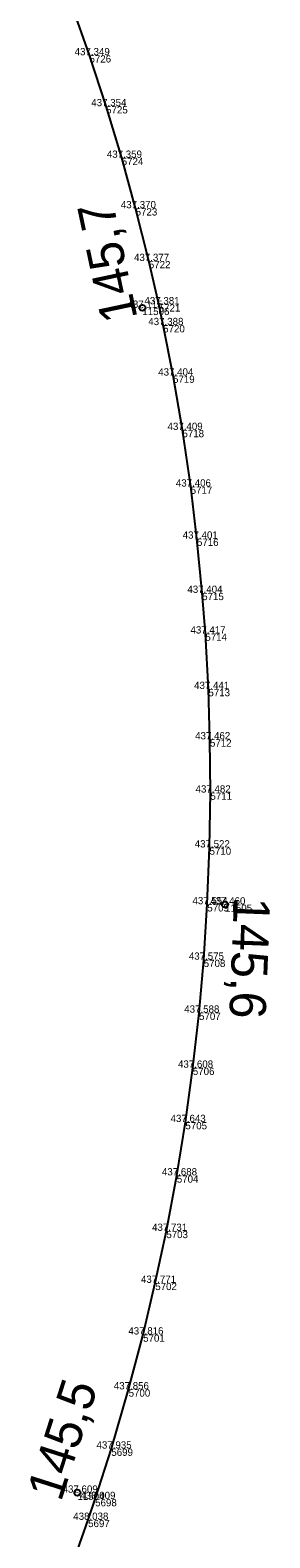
# Model space of a CAD drawing. Extents: x -654154 to -652650, y -1166925 to -1164904.
# Drawn here: x -652689.6 to -652650, y -1166664.4 to -1166415.2 of the extents above; entities that cross this region are included whole.
import ezdxf

# ---------------------------------------------------------------- set-up
doc = ezdxf.new("R2010")
doc.units = 0
for name, color, linetype in [('Vrstva 1', 7, 'Continuous'), ('Vrstva 60', 7, 'Continuous'), ('Vrstva 61', 7, 'Continuous'), ('Vrstva 7', 7, 'Continuous')]:
    doc.layers.add(name, color=color, linetype=linetype)

msp = doc.modelspace()

# ---------------------------------------------------------------- linework, layer by layer
at = {"layer": 'Vrstva 1'}
msp.add_lwpolyline([(-652682.15, -1166667.42), (-652680.05, -1166661.47), (-652678.89, -1166658.03), (-652676.22, -1166649.69), (-652673.36, -1166639.9), (-652670.96, -1166630.83), (-652668.96, -1166622.29), (-652667.13, -1166613.7), (-652665.4, -1166604.53), (-652663.98, -1166595.71), (-652662.75, -1166586.73), (-652661.72, -1166577.63), (-652660.95, -1166568.88), (-652660.36, -1166559.7), (-652659.99, -1166550.32), (-652659.85, -1166541.24), (-652659.92, -1166532.45), (-652660.18, -1166524.12), (-652660.68, -1166514.95), (-652661.2, -1166508.23), (-652662.07, -1166499.27), (-652663.11, -1166490.66), (-652664.47, -1166481.3), (-652666.02, -1166472.31), (-652667.65, -1166463.97), (-652668.38, -1166460.53), (-652670.02, -1166453.37), (-652672.2, -1166444.65), (-652674.5, -1166436.31), (-652677.08, -1166427.78), (-652679.83, -1166419.36), (-652682.76, -1166411.06)], dxfattribs=at)
at = {"layer": 'Vrstva 60'}
for p, q in [((-652679.83, -1166419.36), (-652679.83, -1166419.36)), ((-652677.08, -1166427.78), (-652677.08, -1166427.78)), ((-652674.5, -1166436.31), (-652674.5, -1166436.31)), ((-652672.2, -1166444.65), (-652672.2, -1166444.65)), ((-652670.02, -1166453.37), (-652670.02, -1166453.37)), ((-652671.09, -1166461.11), (-652671.09, -1166461.11)), ((-652668.38, -1166460.53), (-652668.38, -1166460.53)), ((-652667.65, -1166463.97), (-652667.65, -1166463.97)), ((-652666.02, -1166472.31), (-652666.02, -1166472.31)), ((-652664.47, -1166481.3), (-652664.47, -1166481.3)), ((-652663.11, -1166490.66), (-652663.11, -1166490.66)), ((-652662.07, -1166499.27), (-652662.07, -1166499.27)), ((-652661.2, -1166508.23), (-652661.2, -1166508.23)), ((-652660.68, -1166514.95), (-652660.68, -1166514.95)), ((-652660.18, -1166524.12), (-652660.18, -1166524.12)), ((-652659.92, -1166532.45), (-652659.92, -1166532.45)), ((-652659.85, -1166541.24), (-652659.85, -1166541.24)), ((-652659.99, -1166550.32), (-652659.99, -1166550.32)), ((-652660.36, -1166559.7), (-652660.36, -1166559.7)), ((-652657.42, -1166559.75), (-652657.42, -1166559.75)), ((-652660.95, -1166568.88), (-652660.95, -1166568.88)), ((-652661.72, -1166577.63), (-652661.72, -1166577.63)), ((-652662.75, -1166586.73), (-652662.75, -1166586.73)), ((-652663.98, -1166595.71), (-652663.98, -1166595.71)), ((-652665.4, -1166604.53), (-652665.4, -1166604.53)), ((-652667.13, -1166613.7), (-652667.13, -1166613.7)), ((-652668.96, -1166622.29), (-652668.96, -1166622.29)), ((-652670.96, -1166630.83), (-652670.96, -1166630.83)), ((-652673.36, -1166639.9), (-652673.36, -1166639.9)), ((-652676.22, -1166649.69), (-652676.22, -1166649.69)), ((-652681.82, -1166656.98), (-652681.82, -1166656.98)), ((-652678.89, -1166658.03), (-652678.89, -1166658.03)), ((-652680.05, -1166661.47), (-652680.05, -1166661.47))]:
    msp.add_line(p, q, dxfattribs=at)
at = {"layer": 'Vrstva 7'}
for p, q in [((-652671.08, -1166461.15), (-652671.1, -1166461.06)), ((-652657.42, -1166559.7), (-652657.42, -1166559.8)), ((-652681.83, -1166657.02), (-652681.8, -1166656.93))]:
    msp.add_line(p, q, dxfattribs=at)
for centre in [(-652671.09, -1166461.11), (-652657.42, -1166559.75), (-652681.82, -1166656.98)]:
    msp.add_circle(centre, 0.5, dxfattribs=at)

# ---------------------------------------------------------------- texts
at = {"layer": 'Vrstva 60'}
for s, p in [('5726', (-652679.83, -1166420.56)), ('5725', (-652677.08, -1166428.98)), ('5724', (-652674.5, -1166437.51)), ('5723', (-652672.2, -1166445.85)), ('5722', (-652670.02, -1166454.57)), ('11506', (-652671.09, -1166462.31)), ('5721', (-652668.38, -1166461.73)), ('5720', (-652667.65, -1166465.17)), ('5719', (-652666.02, -1166473.51)), ('5718', (-652664.47, -1166482.5)), ('5717', (-652663.11, -1166491.86)), ('5716', (-652662.07, -1166500.47)), ('5715', (-652661.2, -1166509.43)), ('5714', (-652660.68, -1166516.15)), ('5713', (-652660.18, -1166525.32)), ('5712', (-652659.92, -1166533.65)), ('5711', (-652659.85, -1166542.44)), ('5710', (-652659.99, -1166551.52)), ('5709', (-652660.36, -1166560.9)), ('11505', (-652657.42, -1166560.95)), ('5708', (-652660.95, -1166570.08)), ('5707', (-652661.72, -1166578.83)), ('5706', (-652662.75, -1166587.93)), ('5705', (-652663.98, -1166596.91)), ('5704', (-652665.4, -1166605.73)), ('5703', (-652667.13, -1166614.9)), ('5702', (-652668.96, -1166623.49)), ('5701', (-652670.96, -1166632.03)), ('5700', (-652673.36, -1166641.1)), ('5699', (-652676.22, -1166650.89)), ('11504', (-652681.82, -1166658.18)), ('5698', (-652678.89, -1166659.23)), ('5697', (-652680.05, -1166662.67))]:
    msp.add_text(s, height=1.2, dxfattribs=at).set_placement(p)
at = {"layer": 'Vrstva 61'}
for s, p in [('437.349', (-652682.28, -1166419.36)), ('437.354', (-652679.53, -1166427.78)), ('437.359', (-652676.96, -1166436.31)), ('437.370', (-652674.65, -1166444.65)), ('437.377', (-652672.47, -1166453.37)), ('437.381', (-652670.74, -1166460.53)), ('437.115', (-652673.55, -1166461.11)), ('437.388', (-652670.11, -1166463.97)), ('437.404', (-652668.47, -1166472.31)), ('437.409', (-652666.93, -1166481.3)), ('437.406', (-652665.56, -1166490.66)), ('437.401', (-652664.43, -1166499.27)), ('437.404', (-652663.65, -1166508.23)), ('437.417', (-652663.14, -1166514.95)), ('437.441', (-652662.54, -1166524.12)), ('437.462', (-652662.37, -1166532.45)), ('437.482', (-652662.3, -1166541.24)), ('437.522', (-652662.44, -1166550.32)), ('437.554', (-652662.81, -1166559.7)), ('437.460', (-652659.87, -1166559.75)), ('437.575', (-652663.41, -1166568.88)), ('437.588', (-652664.17, -1166577.63)), ('437.608', (-652665.2, -1166586.73)), ('437.643', (-652666.43, -1166595.71)), ('437.688', (-652667.86, -1166604.53)), ('437.731', (-652669.49, -1166613.7)), ('437.771', (-652671.32, -1166622.29)), ('437.816', (-652673.41, -1166630.83)), ('437.856', (-652675.81, -1166639.9)), ('437.935', (-652678.67, -1166649.69)), ('437.609', (-652684.27, -1166656.98)), ('438.009', (-652681.34, -1166658.03)), ('438.038', (-652682.51, -1166661.47))]:
    msp.add_text(s, height=1.2, dxfattribs=at).set_placement(p)
at = {"layer": 'Vrstva 7'}
for s, rotation, p in [('145,7', 101.9558, (-652671.87, -1166462.79)), ('145,6', 267.7296, (-652655.94, -1166558.43)), ('145,5', 72.2416, (-652684.55, -1166658.63))]:
    msp.add_text(s, height=6, rotation=rotation, dxfattribs=at).set_placement(p)

doc.saveas('drawing.dxf')
